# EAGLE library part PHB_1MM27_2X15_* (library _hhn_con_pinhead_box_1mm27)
Pin Header Box-Type, 1.27mm/0.5"/50mil Pitch, 2x15 Circuits Note: see library description for an important note about THT-version
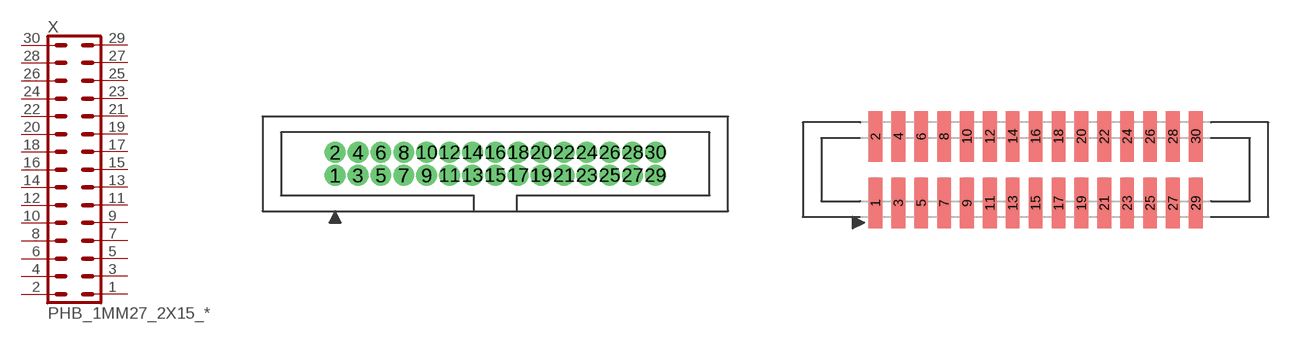
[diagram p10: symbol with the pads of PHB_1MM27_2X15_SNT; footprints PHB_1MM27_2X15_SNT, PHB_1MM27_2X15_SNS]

Designator prefix X

## PHB_1MM27_2X15_SNT  [PHB_1MM27_2X15_SNT]
1  1  pas
2  2  pas
3  3  pas
4  4  pas
5  5  pas
6  6  pas
7  7  pas
8  8  pas
9  9  pas
10  10  pas
11  11  pas
12  12  pas
13  13  pas
14  14  pas
15  15  pas
16  16  pas
17  17  pas
18  18  pas
19  19  pas
20  20  pas
21  21  pas
22  22  pas
23  23  pas
24  24  pas
25  25  pas
26  26  pas
27  27  pas
28  28  pas
29  29  pas
30  30  pas

## PHB_1MM27_2X15_SNS  [PHB_1MM27_2X15_SNS]
Pads as for PHB_1MM27_2X15_SNT

## Footprint PHB_1MM27_2X15_SNT (pad centres in mm)
Pin Header Box-Type, 1.27mm Pitch, 2x15 circuits, Straight, No Locking, THT Important Note: Diameter in this lbr is set to a specific value (NOT 'auto' = 0), this is ignored by actual eagle versions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
drill 0.65 pad 1 round: 1 -8.89,-0.635; 2 -8.89,0.635; 3 -7.62,-0.635; 4 -7.62,0.635; 5 -6.35,-0.635; 6 -6.35,0.635; 7 -5.08,-0.635; 8 -5.08,0.635; 9 -3.81,-0.635; 10 -3.81,0.635; 11 -2.54,-0.635; 12 -2.54,0.635; 13 -1.27,-0.635; 14 -1.27,0.635; 15 0,-0.635; 16 0,0.635; 17 1.27,-0.635; 18 1.27,0.635; 19 2.54,-0.635; 20 2.54,0.635; 21 3.81,-0.635; 22 3.81,0.635; 23 5.08,-0.635; 24 5.08,0.635; 25 6.35,-0.635; 26 6.35,0.635; 27 7.62,-0.635; 28 7.62,0.635; 29 8.89,-0.635; 30 8.89,0.635

## Footprint PHB_1MM27_2X15_SNS (pad centres in mm)
Pin Header Box-Type, 1.27mm Pitch, 2x15 circuits, Straight, No Locking, SMT
smd 0.76 x 2.8: 1 -8.89,-1.85; 2 -8.89,1.85; 3 -7.62,-1.85; 4 -7.62,1.85; 5 -6.35,-1.85; 6 -6.35,1.85; 7 -5.08,-1.85; 8 -5.08,1.85; 9 -3.81,-1.85; 10 -3.81,1.85; 11 -2.54,-1.85; 12 -2.54,1.85; 13 -1.27,-1.85; 14 -1.27,1.85; 15 0,-1.85; 16 0,1.85; 17 1.27,-1.85; 18 1.27,1.85; 19 2.54,-1.85; 20 2.54,1.85; 21 3.81,-1.85; 22 3.81,1.85; 23 5.08,-1.85; 24 5.08,1.85; 25 6.35,-1.85; 26 6.35,1.85; 27 7.62,-1.85; 28 7.62,1.85; 29 8.89,-1.85; 30 8.89,1.85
